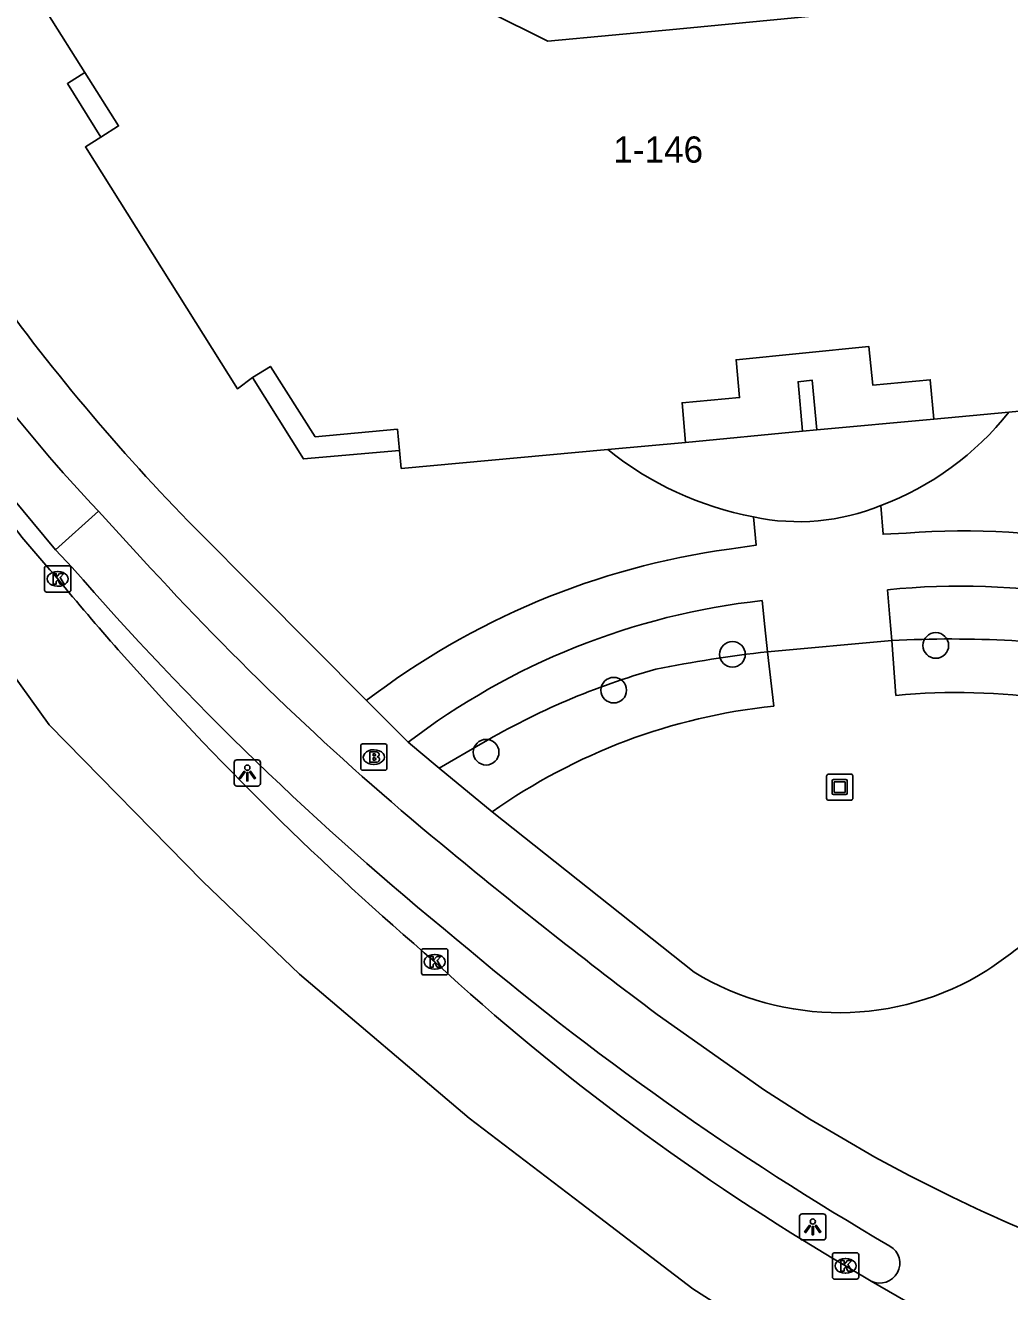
# Model space of a CAD drawing. Extents: x 160026 to 161302, y 384757 to 385701.
# Drawn here: x 160311.97 to 160349.49, y 384832.25 to 384880.56 of the extents above; entities that cross this region are included whole.
import ezdxf

# ---------------------------------------------------------------- set-up
doc = ezdxf.new("R2010")
doc.units = 0
for name, color, linetype in [('IMGEO_Boom', 7, 'Continuous'), ('IMGEO_Brandkraan', 7, 'Continuous'), ('IMGEO_Fietspad_gesloten', 7, 'Continuous'), ('IMGEO_Fietspad_open', 7, 'Continuous'), ('IMGEO_Grasland_overig', 7, 'Continuous'), ('IMGEO_Haag', 7, 'Continuous'), ('IMGEO_Kolk', 7, 'Continuous'), ('IMGEO_Kunstobject', 7, 'Continuous'), ('IMGEO_Lichtpunt', 7, 'Continuous'), ('IMGEO_Pand', 7, 'Continuous'), ('IMGEO_Pand_nummerreeks', 7, 'Continuous'), ('IMGEO_Rijbaan_regionaal_gesloten', 7, 'Continuous'), ('IMGEO_Voetpad_open', 7, 'Continuous')]:
    doc.layers.add(name, color=color, linetype=linetype)

msp = doc.modelspace()

# ---------------------------------------------------------------- linework, layer by layer
at = {"layer": 'IMGEO_Boom'}
for centre in [(160346.678, 384856.903), (160338.926, 384856.564), (160334.399, 384855.197), (160329.534, 384852.832)]:
    msp.add_circle(centre, 0.489, dxfattribs=at)
at = {"layer": 'IMGEO_Brandkraan'}
for p, q in [((160324.753, 384852.219), (160324.753, 384853.071)), ((160324.828, 384853.145), (160325.68, 384853.145)), ((160325.241, 384852.925), (160325.266, 384852.925)), ((160325.754, 384853.071), (160325.754, 384852.219)), ((160325.68, 384852.145), (160324.828, 384852.145)), ((160325.264, 384852.365), (160325.239, 384852.365))]:
    msp.add_line(p, q, dxfattribs=at)
for points in [[(160324.753, 384852.219), (160324.753, 384853.071)], [(160324.828, 384853.145), (160325.68, 384853.145)], [(160325.754, 384853.071), (160325.754, 384852.219)], [(160325.101, 384852.845), (160325.101, 384852.445), (160325.314, 384852.445)], [(160325.332, 384852.845), (160325.101, 384852.845)], [(160325.28, 384852.764), (160325.226, 384852.764), (160325.226, 384852.688)], [(160325.226, 384852.688), (160325.279, 384852.688)], [(160325.288, 384852.612), (160325.226, 384852.612), (160325.226, 384852.531)], [(160325.226, 384852.531), (160325.288, 384852.531)], [(160325.68, 384852.145), (160324.828, 384852.145)]]:
    msp.add_lwpolyline(points, dxfattribs=at)
for centre, radius, start, end in [((160324.83, 384853.069), 0.0765, 91.552, 178.448), ((160324.83, 384853.069), 0.0765, 91.552, 178.448), ((160325.678, 384853.069), 0.0765, 1.552, 88.448), ((160325.678, 384853.069), 0.0765, 1.552, 88.448), ((160325.281, 384852.726), 0.0379, 267.8285, 90.9355), ((160325.289, 384852.571), 0.0404, 269.8759, 90.5077), ((160325.32, 384852.696), 0.251, 268.6676, 293.5347), ((160325.336, 384852.7), 0.145, 59.4692, 91.5367), ((160325.361, 384852.747), 0.0922, 285.5137, 58.1501), ((160325.366, 384852.555), 0.105, 301.3115, 78.989), ((160324.83, 384852.221), 0.0765, 181.552, 268.448), ((160324.83, 384852.221), 0.0765, 181.552, 268.448), ((160325.678, 384852.221), 0.0765, 271.552, 358.448), ((160325.678, 384852.221), 0.0765, 271.552, 358.448)]:
    msp.add_arc(centre, radius, start, end, dxfattribs=at)
for centre, major_axis, ratio, start_param, end_param in [((160325.24, 384852.645), (-0.387, 0.002), 0.722429, 4.712389, 7.853982), ((160325.265, 384852.645), (-0.39, 0.002), 0.717154, 1.570796, 4.712389)]:
    msp.add_ellipse(centre, major_axis=major_axis, ratio=ratio, start_param=start_param, end_param=end_param, dxfattribs=at)
at = {"layer": 'IMGEO_Fietspad_gesloten'}
for points in [[(160313.115, 384860.554), (160314.757, 384862.024)], [(160314.757, 384862.024), (160316.744, 384859.857)], [(160313.752, 384859.88), (160313.115, 384860.554)], [(160336.056, 384842.83), (160340.145, 384839.943), (160341.87, 384838.837), (160343.093, 384838.118), (160344.359, 384837.391), (160345.656, 384836.689), (160346.939, 384836.047)]]:
    msp.add_lwpolyline(points, dxfattribs=at)
for centre, radius, start, end in [((160403.101, 384937.543), 118.384, 220.99742, 230.87497), ((160398.085, 384934.38), 110.318, 222.49518, 230.68396), ((160462.777, 385011.709), 211.136, 230.39793, 233.11672), ((160401.69, 384931.643), 112.947, 229.5413, 239.83243), ((160371.672, 384885.723), 55.493, 243.5316, 249.4103), ((160344.55, 384833.339), 0.756, 243.7581, 59.7893)]:
    msp.add_arc(centre, radius, start, end, dxfattribs=at)
at = {"layer": 'IMGEO_Fietspad_open'}
msp.add_lwpolyline([(160308.907, 384865.615), (160313.115, 384860.554)], dxfattribs=at)
msp.add_arc((160353.936, 384899.394), 54.143, 216.9187, 223.6462, dxfattribs=at)
at = {"layer": 'IMGEO_Grasland_overig'}
for points in [[(160314.849, 384876.296), (160313.57, 384878.333), (160314.238, 384878.762)], [(160326.228, 384864.34), (160322.571, 384864.019), (160320.634, 384867.121)]]:
    msp.add_lwpolyline(points, dxfattribs=at)
at = {"layer": 'IMGEO_Haag'}
msp.add_lwpolyline([(160329.413, 384853.187), (160327.746, 384852.228)], dxfattribs=at)
for centre, radius, start, end in [((160347.246, 384814.425), 42.725, 80.72, 93.0162), ((160345.927, 384806.588), 50.395, 96.4494, 101.3521), ((160343.624, 384828.98), 28.07, 105.7457, 120.4164)]:
    msp.add_arc(centre, radius, start, end, dxfattribs=at)
at = {"layer": 'IMGEO_Kolk'}
for p, q in [((160312.702, 384859.015), (160312.702, 384859.867)), ((160312.777, 384859.941), (160313.629, 384859.941)), ((160313.19, 384859.721), (160313.215, 384859.721)), ((160313.703, 384859.867), (160313.703, 384859.015)), ((160313.629, 384858.941), (160312.777, 384858.941)), ((160313.213, 384859.161), (160313.188, 384859.161)), ((160327.076, 384844.41), (160327.076, 384845.262)), ((160327.151, 384845.336), (160328.003, 384845.336)), ((160328.077, 384845.262), (160328.077, 384844.41)), ((160327.564, 384845.116), (160327.589, 384845.116)), ((160328.003, 384844.336), (160327.151, 384844.336)), ((160327.587, 384844.556), (160327.562, 384844.556)), ((160342.736, 384832.812), (160342.736, 384833.664)), ((160342.811, 384833.738), (160343.663, 384833.738)), ((160343.737, 384833.664), (160343.737, 384832.812)), ((160343.224, 384833.518), (160343.249, 384833.518)), ((160343.663, 384832.738), (160342.811, 384832.738)), ((160343.247, 384832.958), (160343.222, 384832.958))]:
    msp.add_line(p, q, dxfattribs=at)
for points in [[(160312.702, 384859.015), (160312.702, 384859.867)], [(160312.777, 384859.941), (160313.629, 384859.941)], [(160313.703, 384859.867), (160313.703, 384859.015)], [(160313.023, 384859.641), (160313.146, 384859.641), (160313.146, 384859.49), (160313.276, 384859.641), (160313.44, 384859.641), (160313.294, 384859.49), (160313.447, 384859.241), (160313.295, 384859.241), (160313.21, 384859.405), (160313.146, 384859.338), (160313.146, 384859.241), (160313.023, 384859.241), (160313.023, 384859.641)], [(160313.629, 384858.941), (160312.777, 384858.941)], [(160327.076, 384844.41), (160327.076, 384845.262)], [(160327.151, 384845.336), (160328.003, 384845.336)], [(160328.077, 384845.262), (160328.077, 384844.41)], [(160327.397, 384845.036), (160327.52, 384845.036), (160327.52, 384844.885), (160327.65, 384845.036), (160327.814, 384845.036), (160327.668, 384844.885), (160327.821, 384844.636), (160327.669, 384844.636), (160327.584, 384844.8), (160327.52, 384844.733), (160327.52, 384844.636), (160327.397, 384844.636), (160327.397, 384845.036)], [(160328.003, 384844.336), (160327.151, 384844.336)], [(160342.736, 384832.812), (160342.736, 384833.664)], [(160342.811, 384833.738), (160343.663, 384833.738)], [(160343.737, 384833.664), (160343.737, 384832.812)], [(160343.057, 384833.438), (160343.18, 384833.438), (160343.18, 384833.287), (160343.31, 384833.438), (160343.474, 384833.438), (160343.328, 384833.287), (160343.481, 384833.038), (160343.329, 384833.038), (160343.244, 384833.202), (160343.18, 384833.135), (160343.18, 384833.038), (160343.057, 384833.038), (160343.057, 384833.438)], [(160343.663, 384832.738), (160342.811, 384832.738)]]:
    msp.add_lwpolyline(points, dxfattribs=at)
for centre, start, end in [((160312.779, 384859.865), 91.552, 178.448), ((160312.779, 384859.865), 91.552, 178.448), ((160313.627, 384859.865), 1.552, 88.448), ((160313.627, 384859.865), 1.552, 88.448), ((160312.779, 384859.017), 181.552, 268.448), ((160312.779, 384859.017), 181.552, 268.448), ((160313.627, 384859.017), 271.552, 358.448), ((160313.627, 384859.017), 271.552, 358.448), ((160327.153, 384845.26), 91.552, 178.448), ((160327.153, 384845.26), 91.552, 178.448), ((160328.001, 384845.26), 1.552, 88.448), ((160328.001, 384845.26), 1.552, 88.448), ((160327.153, 384844.412), 181.552, 268.448), ((160327.153, 384844.412), 181.552, 268.448), ((160328.001, 384844.412), 271.552, 358.448), ((160328.001, 384844.412), 271.552, 358.448), ((160342.813, 384833.662), 91.552, 178.448), ((160342.813, 384833.662), 91.552, 178.448), ((160343.661, 384833.662), 1.552, 88.448), ((160343.661, 384833.662), 1.552, 88.448), ((160342.813, 384832.814), 181.552, 268.448), ((160342.813, 384832.814), 181.552, 268.448), ((160343.661, 384832.814), 271.552, 358.448), ((160343.661, 384832.814), 271.552, 358.448)]:
    msp.add_arc(centre, 0.0765, start, end, dxfattribs=at)
for centre, major_axis, ratio, start_param, end_param in [((160313.189, 384859.441), (-0.387, 0.002), 0.722429, 4.712389, 7.853982), ((160313.214, 384859.441), (-0.39, 0.002), 0.717154, 1.570796, 4.712389), ((160327.563, 384844.836), (-0.387, 0.002), 0.722429, 4.712389, 7.853982), ((160327.588, 384844.836), (-0.39, 0.002), 0.717154, 1.570796, 4.712389), ((160343.223, 384833.238), (-0.387, 0.002), 0.722429, 4.712389, 7.853982), ((160343.248, 384833.238), (-0.39, 0.002), 0.717154, 1.570796, 4.712389)]:
    msp.add_ellipse(centre, major_axis=major_axis, ratio=ratio, start_param=start_param, end_param=end_param, dxfattribs=at)
at = {"layer": 'IMGEO_Kunstobject'}
for p, q in [((160343.431, 384851.999), (160342.59, 384851.999)), ((160343.431, 384851.999), (160342.59, 384851.999)), ((160342.515, 384851.915), (160342.515, 384851.074)), ((160342.515, 384851.915), (160342.515, 384851.074)), ((160342.729, 384851.263), (160342.729, 384851.737)), ((160342.779, 384851.787), (160343.253, 384851.787)), ((160342.809, 384851.687), (160342.809, 384851.313)), ((160343.203, 384851.707), (160342.829, 384851.707)), ((160343.223, 384851.313), (160343.223, 384851.687)), ((160343.303, 384851.737), (160343.303, 384851.263)), ((160343.515, 384851.083), (160343.515, 384851.924)), ((160343.515, 384851.083), (160343.515, 384851.924)), ((160342.599, 384850.999), (160343.44, 384850.999)), ((160342.599, 384850.999), (160343.44, 384850.999)), ((160343.253, 384851.213), (160342.779, 384851.213)), ((160342.829, 384851.293), (160343.203, 384851.293))]:
    msp.add_line(p, q, dxfattribs=at)
for centre, radius, start, end in [((160342.593, 384851.921), 0.0779, 92.4484, 184.2845), ((160342.593, 384851.921), 0.0779, 92.4484, 184.2845), ((160343.437, 384851.921), 0.0779, 2.4484, 94.2845), ((160343.437, 384851.921), 0.0779, 2.4484, 94.2845), ((160342.779, 384851.737), 0.05, 90, 180), ((160342.829, 384851.687), 0.02, 90, 180), ((160343.203, 384851.687), 0.02, 360, 90), ((160343.253, 384851.737), 0.05, 360, 90), ((160342.593, 384851.077), 0.0779, 182.4484, 274.2845), ((160342.593, 384851.077), 0.0779, 182.4484, 274.2845), ((160342.779, 384851.263), 0.05, 180, 270), ((160342.829, 384851.313), 0.02, 180, 270), ((160343.203, 384851.313), 0.02, 270, 0), ((160343.253, 384851.263), 0.05, 270, 0), ((160343.437, 384851.077), 0.0779, 272.4484, 4.2845), ((160343.437, 384851.077), 0.0779, 272.4484, 4.2845)]:
    msp.add_arc(centre, radius, start, end, dxfattribs=at)
at = {"layer": 'IMGEO_Lichtpunt'}
for p, q in [((160319.932, 384852.443), (160319.932, 384851.636)), ((160319.932, 384852.443), (160319.932, 384851.636)), ((160320.834, 384852.538), (160320.026, 384852.538)), ((160320.834, 384852.538), (160320.026, 384852.538)), ((160320.928, 384851.636), (160320.928, 384852.443)), ((160320.928, 384851.636), (160320.928, 384852.443)), ((160320.026, 384851.542), (160320.834, 384851.542)), ((160320.026, 384851.542), (160320.834, 384851.542)), ((160341.487, 384835.13), (160341.487, 384834.323)), ((160341.487, 384835.13), (160341.487, 384834.323)), ((160342.389, 384835.225), (160341.581, 384835.225)), ((160342.389, 384835.225), (160341.581, 384835.225)), ((160342.483, 384834.323), (160342.483, 384835.13)), ((160342.483, 384834.323), (160342.483, 384835.13)), ((160341.581, 384834.229), (160342.389, 384834.229)), ((160341.581, 384834.229), (160342.389, 384834.229))]:
    msp.add_line(p, q, dxfattribs=at)
for points in [[(160320.306, 384852.107), (160320.345, 384852.079), (160320.157, 384851.817), (160320.119, 384851.844), (160320.306, 384852.107)], [(160320.408, 384852.059), (160320.455, 384852.059), (160320.455, 384851.737), (160320.408, 384851.737), (160320.408, 384852.059)], [(160320.518, 384852.079), (160320.556, 384852.106), (160320.743, 384851.844), (160320.704, 384851.816), (160320.518, 384852.079)], [(160341.861, 384834.794), (160341.9, 384834.766), (160341.712, 384834.504), (160341.674, 384834.531), (160341.861, 384834.794)], [(160341.963, 384834.746), (160342.01, 384834.746), (160342.01, 384834.424), (160341.963, 384834.424), (160341.963, 384834.746)], [(160342.073, 384834.766), (160342.111, 384834.793), (160342.298, 384834.531), (160342.259, 384834.503), (160342.073, 384834.766)]]:
    msp.add_lwpolyline(points, dxfattribs=at)
for centre in [(160320.431, 384852.241), (160341.986, 384834.928)]:
    msp.add_circle(centre, 0.0994, dxfattribs=at)
for centre, start, end in [((160320.026, 384852.443), 90, 180), ((160320.026, 384852.443), 90, 180), ((160320.834, 384852.443), 0, 90), ((160320.834, 384852.443), 0, 90), ((160320.026, 384851.636), 180, 270), ((160320.026, 384851.636), 180, 270), ((160320.834, 384851.636), 270, 0), ((160320.834, 384851.636), 270, 360), ((160341.581, 384835.13), 90, 180), ((160341.581, 384835.13), 90, 180), ((160342.389, 384835.13), 0, 90), ((160342.389, 384835.13), 0, 90), ((160341.581, 384834.323), 180, 270), ((160341.581, 384834.323), 180, 270), ((160342.389, 384834.323), 270, 0), ((160342.389, 384834.323), 270, 360)]:
    msp.add_arc(centre, 0.0946, start, end, dxfattribs=at)
at = {"layer": 'IMGEO_Pand'}
for points in [[(160263.984, 384964.064), (160263.836, 384964.253), (160268.96, 384968.505), (160269.964, 384967.297), (160273.8, 384969.701), (160275.654, 384966.755), (160321.243, 384894.325), (160329.612, 384881.079), (160331.889, 384879.95), (160336.787, 384880.403), (160344.076, 384881.104), (160348.95, 384881.561), (160350.96, 384883.052), (160354.249, 384891.334), (160367.44, 384886.086)], [(160313.449, 384881.373), (160312.831, 384880.99), (160314.238, 384878.762)], [(160314.238, 384878.762), (160315.524, 384876.719), (160314.849, 384876.296)], [(160314.849, 384876.296), (160314.258, 384875.92), (160320.051, 384866.694), (160320.634, 384867.121)], [(160337.132, 384864.648), (160337.004, 384866.162), (160339.199, 384866.357), (160339.064, 384867.801), (160344.125, 384868.301), (160344.272, 384866.835), (160346.465, 384867.04), (160346.601, 384865.537)], [(160320.634, 384867.121), (160321.309, 384867.549), (160323.021, 384864.864), (160326.151, 384865.151), (160326.228, 384864.34)], [(160342.136, 384865.131), (160341.959, 384867.023), (160341.426, 384866.963), (160341.6, 384865.079)], [(160349.467, 384865.807), (160357.434, 384866.559), (160357.378, 384867.246)], [(160346.601, 384865.537), (160349.467, 384865.807)], [(160341.6, 384865.079), (160342.136, 384865.131)], [(160334.173, 384864.377), (160337.132, 384864.648)], [(160326.228, 384864.34), (160326.3, 384863.655), (160334.173, 384864.377)]]:
    msp.add_lwpolyline(points, dxfattribs=at)
at = {"layer": 'IMGEO_Rijbaan_regionaal_gesloten'}
for points in [[(160349.294, 384824.771), (160348.837, 384825.071), (160337.416, 384832.359), (160333.153, 384835.618), (160328.889, 384838.877), (160322.424, 384844.359), (160318.734, 384847.905), (160312.883, 384853.877), (160310.304, 384857.441), (160306.471, 384862.604), (160300.332, 384871.781), (160294.079, 384881.132), (160283.38, 384897.128), (160278.721, 384903.829)], [(160344.216, 384832.661), (160343.421, 384833.12), (160343.236, 384833.237)], [(160348.511, 384830.179), (160344.216, 384832.661)]]:
    msp.add_lwpolyline(points, dxfattribs=at)
for centre, radius, start, end in [((160373.602, 384912.304), 80.266, 215.86262, 221.1933), ((160398.914, 384930.263), 111.186, 219.5664, 221.39845), ((160406.333, 384936.758), 121.046, 221.3824, 229.41124), ((160389.948, 384912.674), 92.154, 227.40503, 239.54321)]:
    msp.add_arc(centre, radius, start, end, dxfattribs=at)
at = {"layer": 'IMGEO_Voetpad_open'}
for points in [[(160346.601, 384865.537), (160342.136, 384865.131)], [(160341.6, 384865.079), (160337.132, 384864.648)], [(160345.55, 384861.191), (160344.668, 384861.146), (160344.583, 384862.246)], [(160339.725, 384861.806), (160339.827, 384860.723), (160338.794, 384860.581)], [(160318.454, 384861.365), (160320.856, 384858.945), (160324.968, 384854.802)], [(160344.998, 384857.091), (160344.928, 384857.96), (160344.842, 384859.027)], [(160340.056, 384858.614), (160340.163, 384857.617), (160340.266, 384856.664)], [(160340.266, 384856.664), (160344.998, 384857.091)], [(160344.998, 384857.091), (160345.156, 384854.994)], [(160340.497, 384854.591), (160340.266, 384856.664)], [(160324.968, 384854.802), (160326.563, 384853.21)], [(160327.746, 384852.228), (160326.966, 384852.875), (160326.563, 384853.21)], [(160327.746, 384852.228), (160329.764, 384850.552)], [(160337.463, 384844.437), (160329.764, 384850.552)]]:
    msp.add_lwpolyline(points, dxfattribs=at)
for centre, radius, start, end in [((160373.754, 384915.82), 77.611, 215.31521, 224.5587), ((160340.671, 384872.741), 11.2, 290.4425, 321.7502), ((160342.064, 384874.138), 12.552, 231.0455, 259.259), ((160341.449, 384869.813), 8.19, 257.8511, 292.4994), ((160347.734, 384831.02), 30.25, 64.5832, 94.1396), ((160342.833, 384831.489), 29.371, 97.9042, 127.4637), ((160347.633, 384831.58), 27.588, 64.8639, 95.807), ((160343.01, 384831.692), 27.083, 96.2609, 127.3917), ((160347.521, 384830.775), 24.334, 67.5565, 95.5767), ((160342.836, 384832.096), 22.616, 95.9354, 125.3088), ((160335.801, 384863.447), 22.879, 304.1005, 321.8013), ((160342.992, 384853.592), 10.696, 238.8702, 301.7969)]:
    msp.add_arc(centre, radius, start, end, dxfattribs=at)

# ---------------------------------------------------------------- texts
at = {"layer": 'IMGEO_Pand_nummerreeks'}
msp.add_text('1-146', height=1, rotation=0, dxfattribs=at).set_placement((160334.385, 384875.318))

doc.saveas('drawing.dxf')
